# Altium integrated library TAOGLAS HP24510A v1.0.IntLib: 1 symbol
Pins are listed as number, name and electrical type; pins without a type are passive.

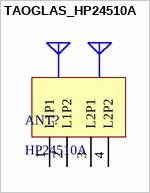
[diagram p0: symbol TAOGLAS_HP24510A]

## TAOGLAS_HP24510A
designator ANT?, comment HP24510A
Passive High Precision GNSS L1/L2 Stacked Patch Ceramic Antenna; ComponentLibStatus: Created; MFG: Taoglas; Temp_High: +85C; Temp_Low: -40C
footprint TAOGLAS_HP24510A (Passive High Precision GNSS L1/L2 Stacked Patch Ceramic Antenna)
pins: 1 L1P1, 2 L1P2, 3 L2P1, 4 L2P2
